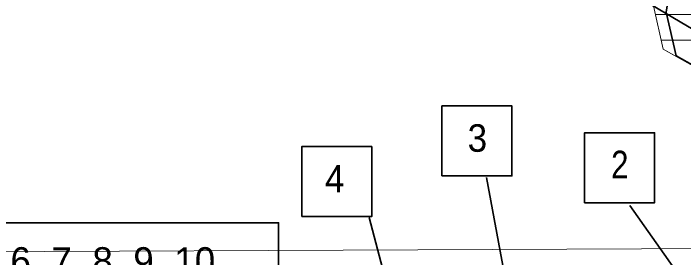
# Model space of a CAD drawing. Extents: x -10.5 to 30.8, y 18.4 to 58.7.
# Drawn here: x -1.16 to 4.05, y 43.96 to 45.86 of the extents above; entities that cross this region are included whole.
import ezdxf
from ezdxf.enums import TextEntityAlignment as Align

# ---------------------------------------------------------------- set-up
doc = ezdxf.new("R2010")
doc.units = 0
doc.header["$LTSCALE"] = 0.08
for name, color, linetype, lineweight in [('16', 7, 'Continuous', 35), ('43', 7, 'Continuous', 13), ('48', 7, 'Continuous', 35), ('51', 7, 'Continuous', 35), ('52', 7, 'Continuous', 13)]:
    doc.layers.add(name, color=color, linetype=linetype, lineweight=lineweight)

msp = doc.modelspace()

# ---------------------------------------------------------------- linework, layer by layer
at = {"layer": '16'}
for p, q in [((10.13057, 42.13922), (3.60875, 46.04227)), ((3.62899, 44.36732), (7.13168, 39.41694))]:
    msp.add_line(p, q, dxfattribs=at)
msp.add_lwpolyline([(3.27697, 44.38978), (3.82157, 44.38978), (3.82157, 44.93433), (3.27697, 44.93433)], close=True, dxfattribs=at)
at = {"layer": '43'}
for p, q in [((3.82655, 45.8548), (4.719, 45.8548)), ((3.82655, 45.8548), (4.719, 45.8548)), ((3.87171, 45.6548), (4.719, 45.6548)), ((3.87171, 45.6548), (4.719, 45.6548))]:
    msp.add_line(p, q, dxfattribs=at)
for points in [[(4.719, 54.19745), (4.22652, 53.1752), (4.1173, 52.76008), (4.16099, 52.12647), (4.02993, 51.7332), (3.89886, 51.25254), (4.00808, 50.79372), (4.13914, 50.26936), (4.05177, 49.85424), (3.94255, 49.37357), (4.22652, 49.08954), (4.22652, 47.72402), (4.08453, 47.36352), (3.83333, 46.77361), (3.77873, 46.60975), (3.85518, 46.20555), (3.81149, 45.92152), (3.88794, 45.58287), (4.43403, 45.27699)], [(4.719, 54.19745), (4.22652, 53.1752), (4.1173, 52.76008), (4.16099, 52.12647), (4.02993, 51.7332), (3.89886, 51.25254), (4.00808, 50.79372), (4.13914, 50.26936), (4.05177, 49.85424), (3.94255, 49.37357), (4.22652, 49.08954), (4.22652, 47.72402), (4.08453, 47.36352), (3.83333, 46.77361), (3.77873, 46.60975), (3.85518, 46.20555), (3.81149, 45.92152), (3.88794, 45.58287), (4.43403, 45.27699)], [(3.81149, 45.92152), (3.88794, 45.58287), (4.16099, 45.42993), (4.43403, 45.27699), (4.3958, 45.11313), (4.35758, 44.94927), (4.19921, 44.79087), (4.15006, 44.68709), (4.16099, 44.49045), (4.24836, 44.26104), (4.25382, 44.08079), (4.25928, 43.90054), (4.32481, 43.81315), (4.43403, 43.72575), (4.51594, 43.70937), (4.6462, 43.68977)], [(3.81149, 45.92152), (3.88794, 45.58287), (4.16099, 45.42993), (4.43403, 45.27699), (4.3958, 45.11313), (4.35758, 44.94927), (4.19921, 44.79087), (4.15006, 44.68709), (4.16099, 44.49045), (4.24836, 44.26104), (4.25382, 44.08079), (4.25928, 43.90054), (4.32481, 43.81315), (4.43403, 43.72575), (4.51594, 43.70937), (4.6462, 43.68977)]]:
    msp.add_lwpolyline(points, dxfattribs=at)
at = {"layer": '48'}
msp.add_lwpolyline([(4.819, 53.99619), (4.32652, 53.1252), (4.2173, 52.71008), (4.26099, 52.07647), (4.12993, 51.6832), (3.99886, 51.20254), (4.10808, 50.74372), (4.23914, 50.21936), (4.15177, 49.80424), (4.04255, 49.32357), (4.32652, 49.03954), (4.32652, 47.67402), (4.18453, 47.31352), (3.93333, 46.72361), (3.87873, 46.55975), (3.95518, 46.15555), (3.91149, 45.87152), (3.98794, 45.53287), (4.53403, 45.22699)], dxfattribs=at)
at = {"layer": '51'}
for p, q in [((2.51512, 44.5862), (4.33772, 34.70325)), ((3.62899, 44.36732), (7.13168, 39.41694)), ((1.60114, 44.27412), (4.66478, 32.90359))]:
    msp.add_line(p, q, dxfattribs=at)
for points in [[(2.16736, 44.59792), (2.71196, 44.59792), (2.71196, 45.14247), (2.16736, 45.14247)], [(3.27697, 44.38978), (3.82157, 44.38978), (3.82157, 44.93433), (3.27697, 44.93433)], [(1.07833, 44.28128), (1.62293, 44.28128), (1.62293, 44.82584), (1.07833, 44.82584)], [(-1.9563, 43.22066), (0.89782, 43.22066), (0.89782, 44.23436), (-1.9563, 44.23436)]]:
    msp.add_lwpolyline(points, close=True, dxfattribs=at)
at = {"layer": '52'}
msp.add_lwpolyline([(-9.61515, 43.9701), (10.09299, 44.05995), (15.25486, 44.08411), (20.41679, 44.0914), (25.57871, 44.0818), (29.5768, 44.0613)], dxfattribs=at)

# ---------------------------------------------------------------- texts
at = {"layer": '16', "width": 0.85}
msp.add_text('2', height=0.2142, dxfattribs=at).set_placement((3.55074, 44.58007), align=Align.CENTER)
at = {"layer": '51', "width": 0.95}
for s, p in [('3', (2.44364, 44.78581)), ('4', (1.33465, 44.46917))]:
    msp.add_text(s, height=0.2142, dxfattribs=at).set_placement(p, align=Align.CENTER)
at = {"layer": '51'}
msp.add_text('5, 6, 7, 8, 9, 10', height=0.2142, dxfattribs=at).set_placement((-0.54942, 43.82928), align=Align.CENTER)

doc.saveas('drawing.dxf')
